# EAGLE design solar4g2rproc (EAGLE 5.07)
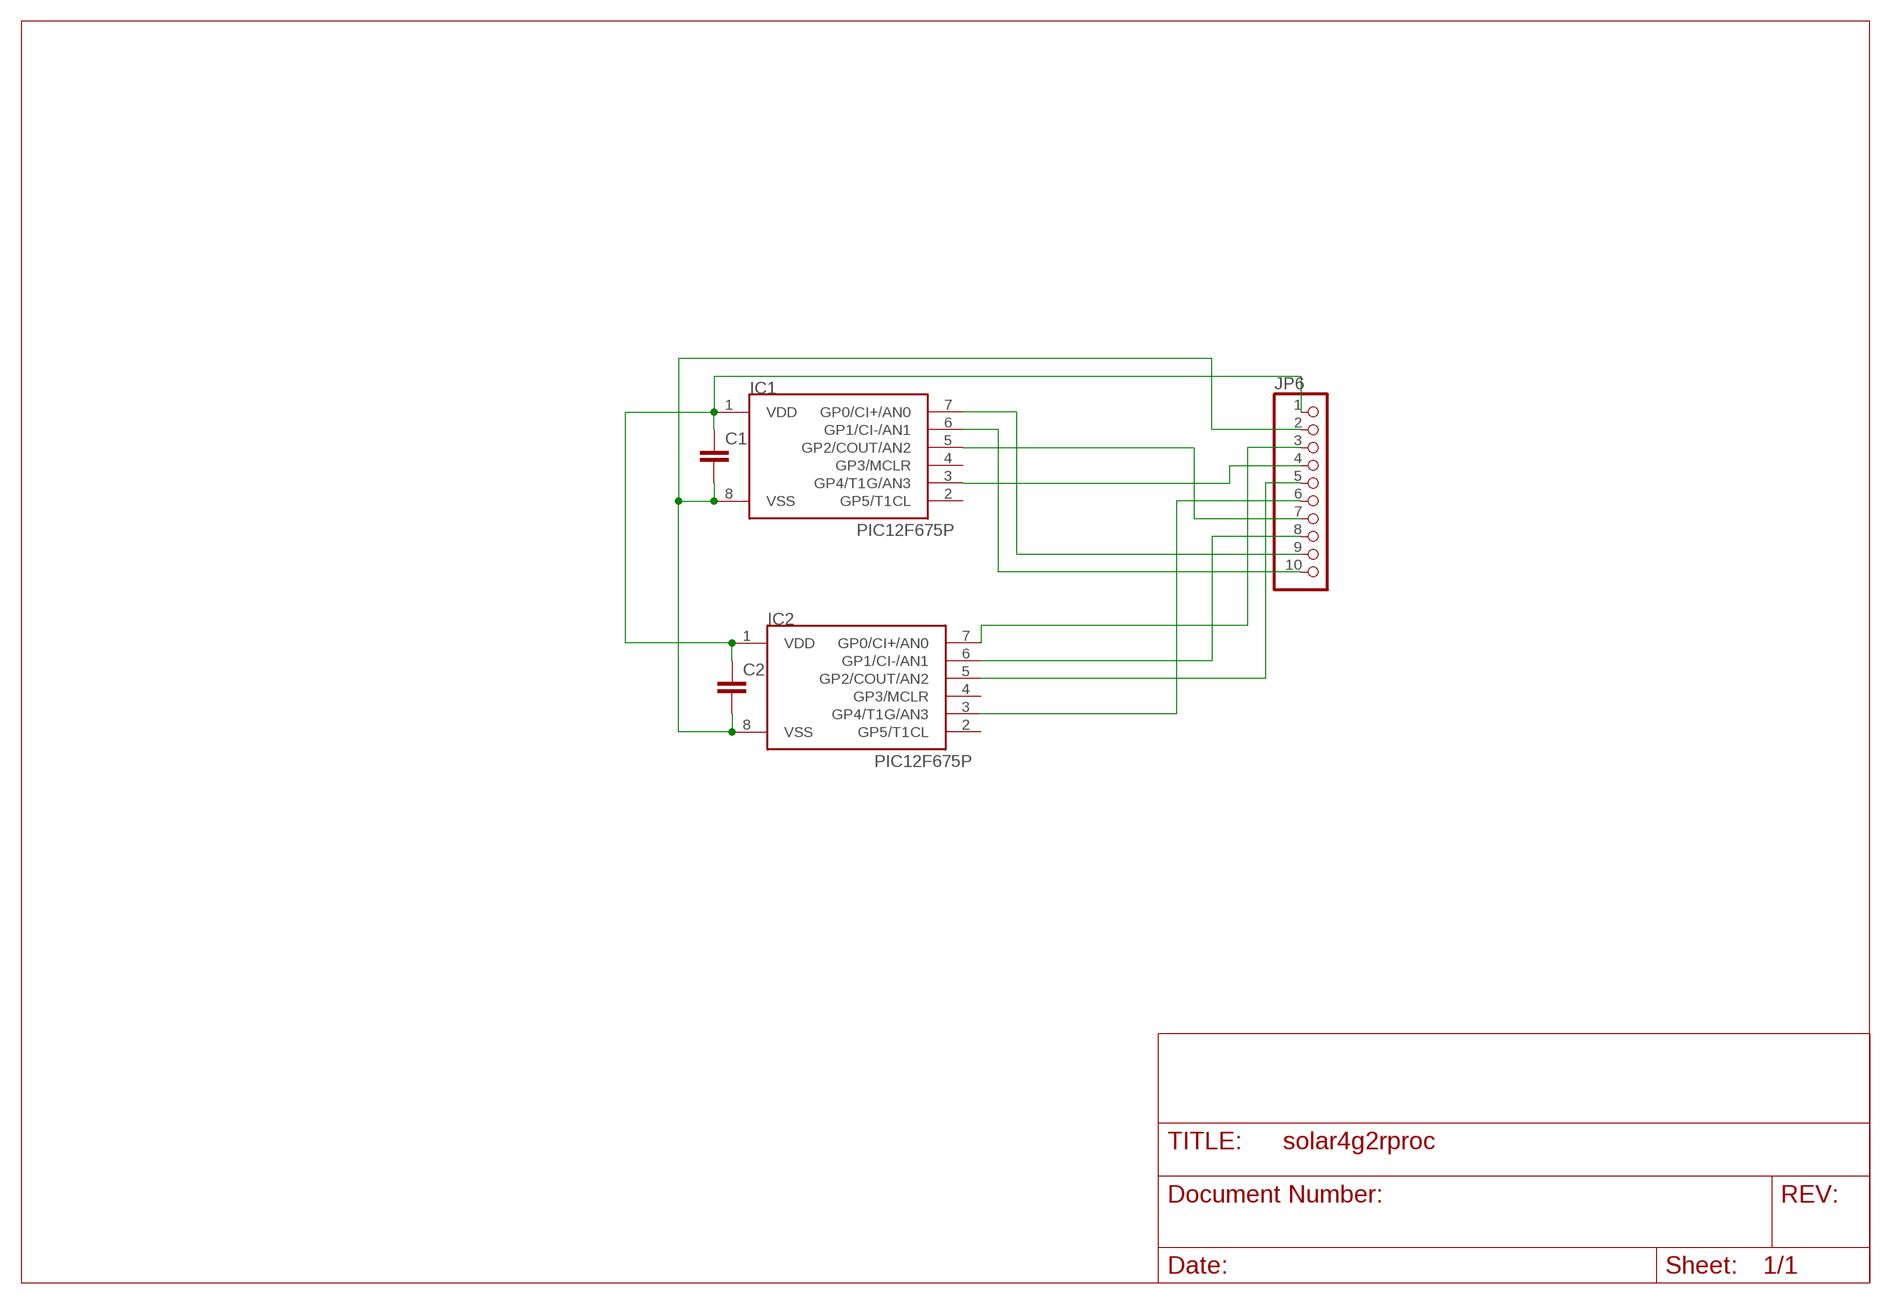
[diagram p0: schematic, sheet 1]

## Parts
C1  C-EUC1206  [C1206]
C2  C-EUC1206  [C1206]
IC1  PIC12F675P  [DIL8]
IC2  PIC12F675P  [DIL8]
JP6  PINHD-1X10  [1X10]

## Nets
EAST: IC1.5(GP2/COUT/AN2) JP6.7
EWLED: IC1.6(GP1/CI-/AN1) JP6.10
EWSENS: IC1.7(GP0/CI+/AN0) JP6.9
N$3: IC2.6(GP1/CI-/AN1) JP6.8
NORT: IC2.5(GP2/COUT/AN2) JP6.5
NSSENS: IC2.7(GP0/CI+/AN0) JP6.3
SUD: IC2.3(GP4/T1G/AN3) JP6.6
V+: C1.1 C2.1 IC1.1(VDD) IC2.1(VDD) JP6.1
V-: C1.2 C2.2 IC1.8(VSS) IC2.8(VSS) JP6.2
WEST: IC1.3(GP4/T1G/AN3) JP6.4
Unconnected: IC1.2(GP5/T1CL) IC1.4(GP3/MCLR) IC2.2(GP5/T1CL) IC2.4(GP3/MCLR)

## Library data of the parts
C1 C2 = rcl:C-EU: CAPACITOR, European symbol
IC1 IC2 = microchip-5:PIC12F6*: uPC nW 1k Program Flash memory 2x Timer Comparator 10b A/D converter/ 4xIN
JP6 = pinhead:PINHD-1X10: PIN HEADER

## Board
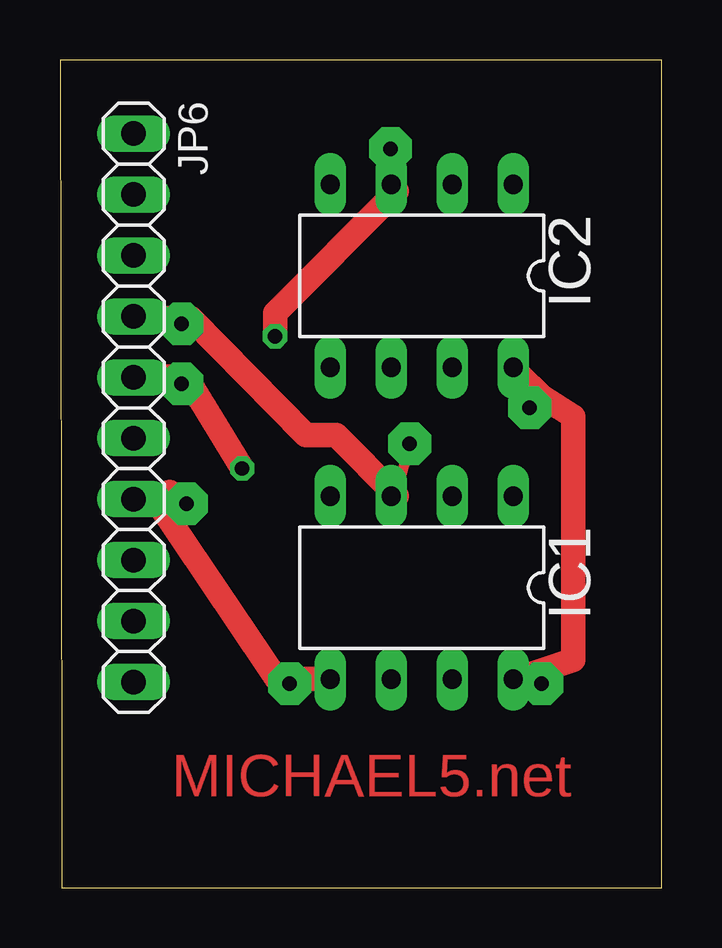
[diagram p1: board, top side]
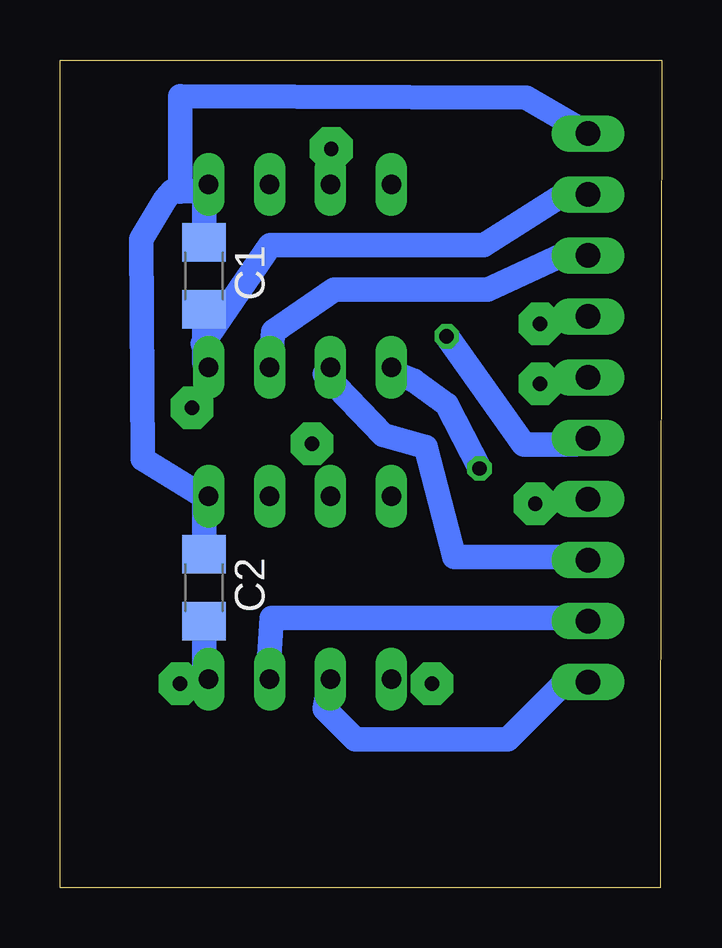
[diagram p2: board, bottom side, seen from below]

Size 25.07 x 34.5 mm. Coordinates in mm from the lower left corner, seen from the top.
Outline: 0.07,0 25.07,0 25.07,34.5 0,34.5 0.07,4.5 0.07,0
Copper layers (1*16): Top 0.035mm / dielectric 1.5mm / Bottom 0.035mm
Design rules "default *": minimum track width 40mil, minimum drill 30mil, track to track 8mil, track to pad 8mil, pad to pad 8mil, via to via 8mil, smd to smd 8mil, copper to edge 40mil, drill to drill 8mil, minimum pad ring 10mil, minimum via ring 8mil, stop-mask expansion 4mil, vias tented up to drill 0mil, thermal gap 10mil

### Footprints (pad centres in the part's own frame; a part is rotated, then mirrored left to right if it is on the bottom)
C1206 = smd 1.6 x 1.8: 1 -1.4,0; 2 1.4,0
DIL8 = drill 0.8 long: 1 -3.81,-3.81; 2 -1.27,-3.81; 3 1.27,-3.81; 4 3.81,-3.81; 5 3.81,3.81; 6 1.27,3.81; 7 -1.27,3.81; 8 -3.81,3.81
1X10 = drill 1.016 long: 1 -11.43,0; 2 -8.89,0; 3 -6.35,0; 4 -3.81,0; 5 -1.27,0; 6 1.27,0; 7 3.81,0; 8 6.35,0; 9 8.89,0; 10 11.43,0

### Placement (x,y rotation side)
C1  19.07,25.5 270 bottom
C2  19.07,12.5 270 bottom
IC1  15.07,12.5 180 top
IC2  15.07,25.5 180 top
JP6  3.07,20 270 top

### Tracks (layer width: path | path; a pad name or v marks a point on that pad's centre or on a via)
EAST  (via drill 0.6 pad 1.78)
  Top 0.406: v9.57,8.5 9.57,8.7
  Top 1.016: 4.09,16.02 9,8.71 9.57,8.7 IC1.5 | 4.09,16.02 3.88,16.33 JP6.7 | v5.27,16 4.58,16.5 4.09,16.02
EWLED
  Bottom 1.016: IC1.6 14.04,7.44 12.77,6.17 6.42,6.17 3.88,8.71 JP6.10
EWSENS
  Bottom 1.016: IC1.7 16.38,9.31 16.24,11.25 3.88,11.25 JP6.9
N$3
  Bottom 1.016: IC2.6 14.04,21.41 11.6,18.87 9.83,18.37 8.65,13.79 3.88,13.79 JP6.8
NORT  (via drill 0.6, 0.6 pad 1.78)
  Top 1.016: v7.59,17.47 5.34,21.16 | 5.34,21.16 5.25,21.31 4.08,21.31 JP6.5 | v5.07,21 5.18,21 5.34,21.16
  Bottom 1.016: v7.59,17.47 8.96,20.14 10.33,21.14 11,21.41 IC2.5
NSSENS
  Bottom 1.016: IC2.7 16.18,23.18 13.64,24.92 7.25,24.92 3.88,26.49 JP6.3
SUD  (via drill 0.6, 0.6 pad 1.78)
  Top 1.016: v8.96,22.98 8.96,23.95 14.04,29.03 IC2.3
  Bottom 0.406: v13.77,30.8 13.77,29.34 IC2.3
  Bottom 1.016: v8.96,22.98 5.75,18.47 3.58,18.47 JP6.6
V+
  Bottom 0.406: 20.69,28.7 20.07,29.02
  Bottom 1.016: JP6.1 5.64,32.93 20.07,33 20.07,29.02 | C1.1 19.07,29.12 IC2.1 19.12,29.03 20.39,29.03 20.69,28.7 21.69,27.04 21.62,17.87 19.12,16.33 IC1.1 19.07,16.12 C2.1
V-  (via drill 0.6 pad 1.78)
  Top 0.406: 19.12,8.71 19.86,8.71 v20.07,8.5 | 20.05,20.48 v19.57,20
  Top 1.016: IC1.8 19.12,8.71 21.39,9.48 21.39,19.64 20.05,20.48 19.12,21.41 IC2.8
  Bottom 1.016: JP6.2 3.88,29.03 7.42,26.79 16.31,26.79 19.12,22.68 IC2.8 19.07,21.88 C1.2 | C2.2 19.07,8.88 IC1.8
WEST  (via drill 0.6 pad 1.78)
  Top 0.406: v14.57,18.5 14.07,16.58 IC1.3
  Top 1.016: 5.32,23.75 4.18,23.75 JP6.4 | IC1.3 14.04,16.33 11.5,18.87 10.23,18.87 5.45,23.75 5.32,23.75 | 5.32,23.75 v5.07,23.5

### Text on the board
Top: MICHAEL5.net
